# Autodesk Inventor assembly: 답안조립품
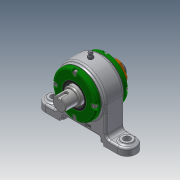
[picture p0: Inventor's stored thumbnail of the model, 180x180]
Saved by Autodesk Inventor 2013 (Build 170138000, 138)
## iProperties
Created: 2019-05
Part Number: 답안조립품
Document SubType Name: Assembly
Designer: user
Author: user
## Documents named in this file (13)
- C:\Users\user\Desktop\490504V1013\답안조립품.iam
- C:\Users\user\Desktop\490504V1013\본체.ipt
- C:\Users\user\Desktop\490504V1013\개스킷.ipt
- C:\Users\user\Desktop\490504V1013\그리스니플 M6.ipt
- 그리스니플  M6.ipt
- C:\Users\user\Desktop\490504V1013\그리스니플개스킷.ipt
- C:\Users\user\Desktop\490504V1013\베어링너트.ipt
- C:\Users\user\Desktop\490504V1013\볼트 M4.ipt
- C:\Users\user\Desktop\490504V1013\앵귤러 볼 베어링 7205.ipt
- C:\Users\user\Desktop\490504V1013\오일 실 28 40 5 B.ipt
- C:\Users\user\Desktop\490504V1013\축.ipt
- C:\Users\user\Desktop\490504V1013\칼라.ipt
- C:\Users\user\Desktop\490504V1013\커버.ipt
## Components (4 placed, 3 different names)
1. 개스킷:1
2. 그리스니플  M6:1
3. 그리스니플개스킷:1
4. 개스킷:2
